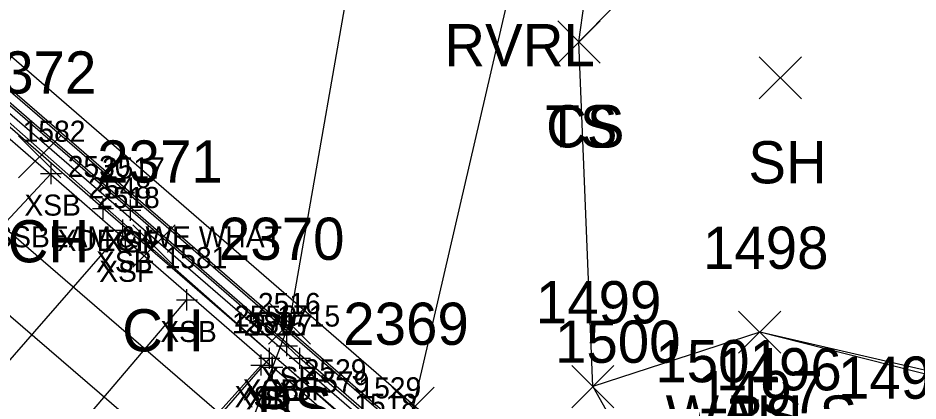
# Model space of a CAD drawing. Extents: x 1459992 to 1461532, y 647785 to 648535.
# Drawn here: x 1461331.07 to 1461373.72, y 648178.67 to 648196.83 of the extents above; entities that cross this region are included whole.
import ezdxf

# ---------------------------------------------------------------- set-up
doc = ezdxf.new("R2010")
doc.units = 0
for name, color, linetype in [('B_A', 7, 'Continuous'), ('B_C', 7, 'Continuous'), ('B_I', 7, 'Continuous'), ('B_TIC', 7, 'Continuous'), ('BB', 7, 'Continuous'), ('BDEFAULT', 7, 'Continuous'), ('BELB', 7, 'Continuous'), ('L_A', 7, 'Continuous'), ('L_I', 7, 'Continuous'), ('L_TIC', 7, 'Continuous'), ('LAWE', 7, 'Continuous'), ('LELB', 7, 'Continuous'), ('LWS', 7, 'Continuous')]:
    doc.layers.add(name, color=color, linetype=linetype)

msp = doc.modelspace()

# ---------------------------------------------------------------- linework, layer by layer
at = {"layer": 'B_TIC'}
for p, q in [((1461332.644, 648189.458), (1461332.72, 648189.458)), ((1461335.105, 648187.79), (1461335.181, 648187.79)), ((1461336.404, 648187.716), (1461336.479, 648187.716)), ((1461336.038, 648186.774), (1461336.114, 648186.774)), ((1461336.165, 648186.32), (1461336.24, 648186.32)), ((1461339.083, 648183.468), (1461339.159, 648183.468)), ((1461343.82, 648181.296), (1461343.895, 648181.296)), ((1461342.988, 648180.7), (1461343.063, 648180.7)), ((1461344.428, 648180.701), (1461344.504, 648180.701)), ((1461342.605, 648180.377), (1461342.68, 648180.377)), ((1461343.119, 648180.272), (1461343.194, 648180.272)), ((1461343.13, 648180.28), (1461343.205, 648180.28))]:
    msp.add_line(p, q, dxfattribs=at)
for points in [[(1461332.641, 648188.958), (1461332.641, 648189.958)], [(1461332.141, 648189.458), (1461333.141, 648189.458)], [(1461335.102, 648187.29), (1461335.102, 648188.29)], [(1461336.4, 648187.216), (1461336.4, 648188.216)], [(1461334.602, 648187.79), (1461335.602, 648187.79)], [(1461335.9, 648187.716), (1461336.9, 648187.716)], [(1461336.035, 648186.274), (1461336.035, 648187.274)], [(1461336.161, 648185.82), (1461336.161, 648186.82)], [(1461335.535, 648186.774), (1461336.535, 648186.774)], [(1461335.661, 648186.32), (1461336.661, 648186.32)], [(1461339.08, 648182.968), (1461339.08, 648183.968)], [(1461338.58, 648183.468), (1461339.58, 648183.468)], [(1461343.816, 648180.796), (1461343.816, 648181.796)], [(1461343.316, 648181.296), (1461344.316, 648181.296)], [(1461342.601, 648179.877), (1461342.601, 648180.877)], [(1461342.984, 648180.2), (1461342.984, 648181.2)], [(1461344.425, 648180.201), (1461344.425, 648181.201)], [(1461342.484, 648180.7), (1461343.484, 648180.7)], [(1461343.115, 648179.772), (1461343.115, 648180.772)], [(1461343.126, 648179.78), (1461343.126, 648180.78)], [(1461343.925, 648180.701), (1461344.925, 648180.701)], [(1461342.101, 648180.377), (1461343.101, 648180.377)], [(1461342.615, 648180.272), (1461343.615, 648180.272)], [(1461342.626, 648180.28), (1461343.626, 648180.28)]]:
    msp.add_lwpolyline(points, dxfattribs=at)
at = {"layer": 'BB'}
for points in [[(1461294.86, 648223.307), (1461364.242, 648163.24)], [(1461361.677, 648166.016), (1461348.554, 648177.299), (1461327.493, 648195.57), (1461324.09, 648198.708), (1461313.449, 648207.484), (1461303.185, 648216.496), (1461300.834, 648218.513)], [(1461361.208, 648165.406), (1461348.067, 648176.515), (1461326.978, 648195.119), (1461323.429, 648198.068), (1461312.601, 648206.996), (1461302.604, 648215.891), (1461300.353, 648217.975)], [(1461357.803, 648164.521), (1461346.033, 648173.409), (1461325.183, 648191.393), (1461321.182, 648194.832), (1461311.295, 648203.276), (1461301.649, 648211.621), (1461295.127, 648216.651)], [(1461323.859, 648180.043), (1461332.641, 648189.458)], [(1461336.035, 648186.774), (1461327.233, 648176.673)], [(1461331.12, 648174.098), (1461339.08, 648183.468)], [(1461342.984, 648180.7), (1461334.2, 648170.626)], [(1461334.279, 648171.093), (1461342.601, 648180.377)]]:
    msp.add_lwpolyline(points, dxfattribs=at)
at = {"layer": 'BDEFAULT'}
for points in [[(1461366.38, 648164.112), (1461295.255, 648225.766)], [(1461362.149, 648166.267), (1461362.72, 648165.994), (1461364.469, 648164.112), (1461295.876, 648223.48), (1461297.915, 648221.839), (1461297.913, 648221.848)], [(1461362.149, 648166.267), (1461297.913, 648221.848)], [(1461361.121, 648166.284), (1461352.416, 648173.806), (1461344.425, 648180.701), (1461343.816, 648181.296), (1461336.4, 648187.716), (1461329.743, 648193.486), (1461322.335, 648200.012), (1461315.377, 648206.043), (1461308.561, 648211.971), (1461301.731, 648217.881), (1461299.043, 648219.999)], [(1461360.363, 648157.144), (1461288.944, 648218.654)], [(1461360.571, 648165.346), (1461356.744, 648168.633), (1461349.668, 648174.685), (1461343.126, 648180.28), (1461343.115, 648180.272), (1461336.161, 648186.32), (1461329.105, 648192.44), (1461321.703, 648198.993), (1461314.797, 648204.994), (1461308.017, 648210.912), (1461301.203, 648216.737)]]:
    msp.add_lwpolyline(points, dxfattribs=at)
at = {"layer": 'BELB'}
msp.add_lwpolyline([(1461362.021, 648164.506), (1461356.918, 648168.766), (1461356.744, 648168.633), (1461346.243, 648178.153), (1461335.102, 648187.79), (1461324.925, 648196.655), (1461312.315, 648207.599), (1461296.583, 648221.232), (1461287.57, 648210.913), (1461301.391, 648198.959), (1461310.883, 648190.676), (1461320.988, 648181.882), (1461328.312, 648175.511), (1461338.631, 648166.593)], dxfattribs=at)
at = {"layer": 'L_TIC'}
for points in [[(1461356.653, 648194.692), (1461358.653, 648196.692)], [(1461358.653, 648194.692), (1461356.653, 648196.692)], [(1461356.653, 648194.692), (1461358.653, 648196.692)], [(1461358.653, 648194.692), (1461356.653, 648196.692)], [(1461366.19, 648192.989), (1461368.19, 648194.989)], [(1461368.19, 648192.989), (1461366.19, 648194.989)], [(1461331.097, 648189.245), (1461333.097, 648191.245)], [(1461333.097, 648189.245), (1461331.097, 648191.245)], [(1461336.519, 648185.024), (1461338.519, 648187.024)], [(1461338.519, 648185.024), (1461336.519, 648187.024)], [(1461342.94, 648181.363), (1461344.94, 648183.363)], [(1461344.94, 648181.363), (1461342.94, 648183.363)], [(1461365.22, 648180.937), (1461367.22, 648182.937)], [(1461367.22, 648180.937), (1461365.22, 648182.937)], [(1461365.22, 648180.937), (1461367.22, 648182.937)], [(1461367.22, 648180.937), (1461365.22, 648182.937)], [(1461357.31, 648178.355), (1461359.31, 648180.355)], [(1461359.31, 648178.355), (1461357.31, 648180.355)], [(1461357.31, 648178.355), (1461359.31, 648180.355)], [(1461359.31, 648178.355), (1461357.31, 648180.355)], [(1461348.799, 648177.335), (1461350.799, 648179.335)], [(1461350.799, 648177.335), (1461348.799, 648179.335)]]:
    msp.add_lwpolyline(points, dxfattribs=at)
at = {"layer": 'LAWE'}
msp.add_lwpolyline([(1461220.159, 648021.615), (1461235.47, 648039.294), (1461252.966, 648048.327), (1461267.663, 648064.216), (1461276.22, 648071.524), (1461288.833, 648087.698), (1461307.75, 648107.551), (1461316.994, 648127.784), (1461326.453, 648138.792), (1461334.868, 648155.88), (1461340.573, 648163.303), (1461349.799, 648178.335), (1461354.706, 648199.541), (1461353.8, 648220.98), (1461352.341, 648246.452), (1461354.078, 648262.219), (1461358.254, 648276.136), (1461371.394, 648295.376), (1461381.983, 648319.016), (1461394.178, 648330.617), (1461418.251, 648335.818), (1461440.86, 648338.789), (1461464.612, 648337.5), (1461486.388, 648342.471)], dxfattribs=at)
at = {"layer": 'LELB'}
for points in [[(1461216.735, 648025.379), (1461232.531, 648043.682), (1461249.111, 648052.696), (1461265.41, 648068.573), (1461273.176, 648074.771), (1461285.769, 648090.042), (1461304.003, 648110.191), (1461314.102, 648129.874), (1461321.787, 648141.876), (1461329.36, 648157.887), (1461338.075, 648167.022), (1461343.94, 648182.363), (1461347.487, 648202.693), (1461348.844, 648222.98), (1461349.522, 648245.94), (1461349.946, 648262.877), (1461353.497, 648277.365), (1461366.77, 648299.226), (1461380.277, 648319.065), (1461391.623, 648332.953), (1461418.599, 648338.961), (1461441.306, 648340.652), (1461465.695, 648340.733), (1461485.923, 648346.235)], [(1461358.31, 648179.355), (1461357.653, 648195.692), (1461360.601, 648216.915), (1461360.157, 648235.422), (1461360.989, 648255.356), (1461365.028, 648278.404), (1461376.071, 648295.04), (1461384.29, 648312.493), (1461396.995, 648324.631), (1461420.097, 648331.579), (1461440.679, 648334.945), (1461465.222, 648335.03), (1461486.95, 648334.589)], [(1461357.653, 648195.692), (1461372.62, 648210.835), (1461379.226, 648235), (1461368.439, 648254.002), (1461374.317, 648275.061), (1461388.077, 648297.078), (1461390.715, 648303.649), (1461401.544, 648316.282), (1461420.081, 648328.389), (1461441.846, 648332.112), (1461465.283, 648329.963)], [(1461395.776, 648145.183), (1461401.217, 648149.693), (1461402.296, 648152.589), (1461400, 648157.981), (1461396.861, 648163.276), (1461393.612, 648165.262), (1461384.114, 648176.457), (1461379.778, 648178.815), (1461366.22, 648181.937)]]:
    msp.add_lwpolyline(points, dxfattribs=at)
at = {"layer": 'LWS'}
msp.add_lwpolyline([(1461395.776, 648145.183), (1461400.322, 648150.694), (1461401.031, 648152.786), (1461398.988, 648157.264), (1461399.256, 648157.952), (1461396.519, 648162.757), (1461393.211, 648163.751), (1461392.781, 648164.345), (1461383.255, 648175.001), (1461379.666, 648178.519), (1461366.22, 648181.937), (1461358.31, 648179.355), (1461359.375, 648177.485)], dxfattribs=at)

# ---------------------------------------------------------------- texts
at = {"layer": 'B_A'}
for s, p in [('XSB', (1461331.377, 648187.458)), ('XDECK', (1461332.944, 648185.79)), ('XSF', (1461335.16, 648185.716)), ('XSB', (1461334.771, 648184.774)), ('XSF', (1461334.921, 648184.32)), ('XSB', (1461337.816, 648181.468)), ('XSF', (1461342.576, 648179.296)), ('XSB', (1461341.721, 648178.7)), ('XSF', (1461343.185, 648178.701)), ('XSB', (1461341.337, 648178.377)), ('XSF', (1461341.875, 648178.272)), ('XSF', (1461341.886, 648178.28))]:
    msp.add_text(s, height=1, dxfattribs=at).set_placement(p)
at = {"layer": 'B_C'}
msp.add_text('TOTAL OF 18 CROSSBEAM & WE WHAT', height=1, dxfattribs=at).set_placement((1461318.165, 648185.958))
at = {"layer": 'B_I'}
for s, p in [('1582', (1461331.294, 648190.958)), ('2530', (1461333.429, 648189.29)), ('2517', (1461335.054, 648189.216)), ('2548', (1461334.405, 648188.274)), ('2518', (1461334.815, 648187.82)), ('1581', (1461338.017, 648184.968)), ('2516', (1461342.442, 648182.796)), ('2550', (1461341.311, 648182.2)), ('1715', (1461343.362, 648182.201)), ('1580', (1461341.211, 648181.877)), ('2515', (1461341.769, 648181.772)), ('1717', (1461342.063, 648181.78)), ('2529', (1461344.61, 648179.653)), ('1579', (1461344.74, 648179.074)), ('1529', (1461347.204, 648178.799)), ('1518', (1461347.004, 648178.015))]:
    msp.add_text(s, height=1, dxfattribs=at).set_placement(p)
at = {"layer": 'L_A'}
for s, p in [('RVRL', (1461351.273, 648194.541)), ('TS', (1461356.062, 648190.692)), ('CS', (1461356.094, 648190.692)), ('SH', (1461365.678, 648188.989)), ('CH', (1461330.585, 648185.245)), ('CH', (1461336.008, 648181.024)), ('BS', (1461342.381, 648177.363)), ('WALLS', (1461361.763, 648176.937)), ('BS', (1461364.661, 648176.937))]:
    msp.add_text(s, height=2, dxfattribs=at).set_placement(p)
at = {"layer": 'L_I'}
for s, p in [('2372', (1461328.837, 648193.245)), ('2371', (1461334.826, 648189.024)), ('2370', (1461340.594, 648185.363)), ('1498', (1461363.527, 648184.937)), ('1498', (1461363.527, 648184.937)), ('1499', (1461355.609, 648182.355)), ('1499', (1461355.609, 648182.355)), ('2369', (1461346.484, 648181.335)), ('1500', (1461356.517, 648180.485)), ('1500', (1461356.517, 648180.485)), ('1500', (1461356.517, 648180.485)), ('1501', (1461361.271, 648179.562)), ('1501', (1461361.271, 648179.562)), ('1496', (1461364.155, 648179.178)), ('1495', (1461369.921, 648178.782)), ('1495', (1461369.921, 648178.782)), ('1497', (1461363.264, 648178.095))]:
    msp.add_text(s, height=2, dxfattribs=at).set_placement(p)

doc.saveas('drawing.dxf')
